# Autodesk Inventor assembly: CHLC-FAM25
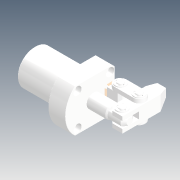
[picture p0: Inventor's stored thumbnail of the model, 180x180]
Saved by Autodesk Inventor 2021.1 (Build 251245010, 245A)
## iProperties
Created: 2019-04
Part Number: CHLC-FAM25
Description: STEP AP214
Document SubType Name: Assembly
Designer: user
Title: CHLC-FAM25.STEP
Revision Number: ÈÎºÎ
Sending System: SolidWorks 2016
Preprocessor: SwSTEP 2.0
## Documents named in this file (10)
- D:\Vault_2016\Projekty\Clamptek\Hydraulic\CHLC\CHLC-25\Inventor\CHLC-FAM25\CHLC-FAM25.iam
- D:\Vault_2016\Projekty\Clamptek\Hydraulic\CHLC\CHLC-25\Inventor\CHLC-FAM25\CHLC-FAM25_ASM.ipt
- D:\Vault_2016\Projekty\Clamptek\Hydraulic\CHLC\CHLC-25\Inventor\CHLC-FAM25\CHLC-FAM25BT.ipt
- D:\Vault_2016\Projekty\Clamptek\Hydraulic\CHLC\CHLC-25\Inventor\CHLC-FAM25\CHLC-25ZC.ipt
- D:\Vault_2016\Projekty\Clamptek\Hydraulic\CHLC\CHLC-25\Inventor\CHLC-FAM25\CHLC-25LG.ipt
- D:\Vault_2016\Projekty\Clamptek\Hydraulic\CHLC\CHLC-25\Inventor\CHLC-FAM25\CHLC-25HSG.ipt
- D:\Vault_2016\Projekty\Clamptek\Hydraulic\CHLC\CHLC-25\Inventor\CHLC-FAM25\CHLC-25CX.ipt
- D:\Vault_2016\Projekty\Clamptek\Hydraulic\CHLC\CHLC-25\Inventor\CHLC-FAM25\CHLC-25DX.ipt
- D:\Vault_2016\Projekty\Clamptek\Hydraulic\CHLC\CHLC-25\Inventor\CHLC-FAM25\CHLC-25KKDC.ipt
- D:\Vault_2016\Projekty\Clamptek\Hydraulic\CHLC\CHLC-25\Inventor\CHLC-FAM25\Ñ¹±Û.ipt
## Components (16 placed, 16 different names)
1. CHLC-FAM25_ASM_1
2. CHLC-FAM25BT_2
3. CHLC-25ZC_3
4. CHLC-25LG_4
5. CHLC-25LG_5
6. CHLC-25HSG_6
7. CHLC-25CX_7
8. CHLC-25CX_8
9. CHLC-25DX_9
10. CHLC-25KKDC_10
11. CHLC-25KKDC_11
12. CHLC-25KKDC_12
13. CHLC-25KKDC_13
14. CHLC-25KKDC_14
15. CHLC-25KKDC_15
16. Ñ¹±Û_16
